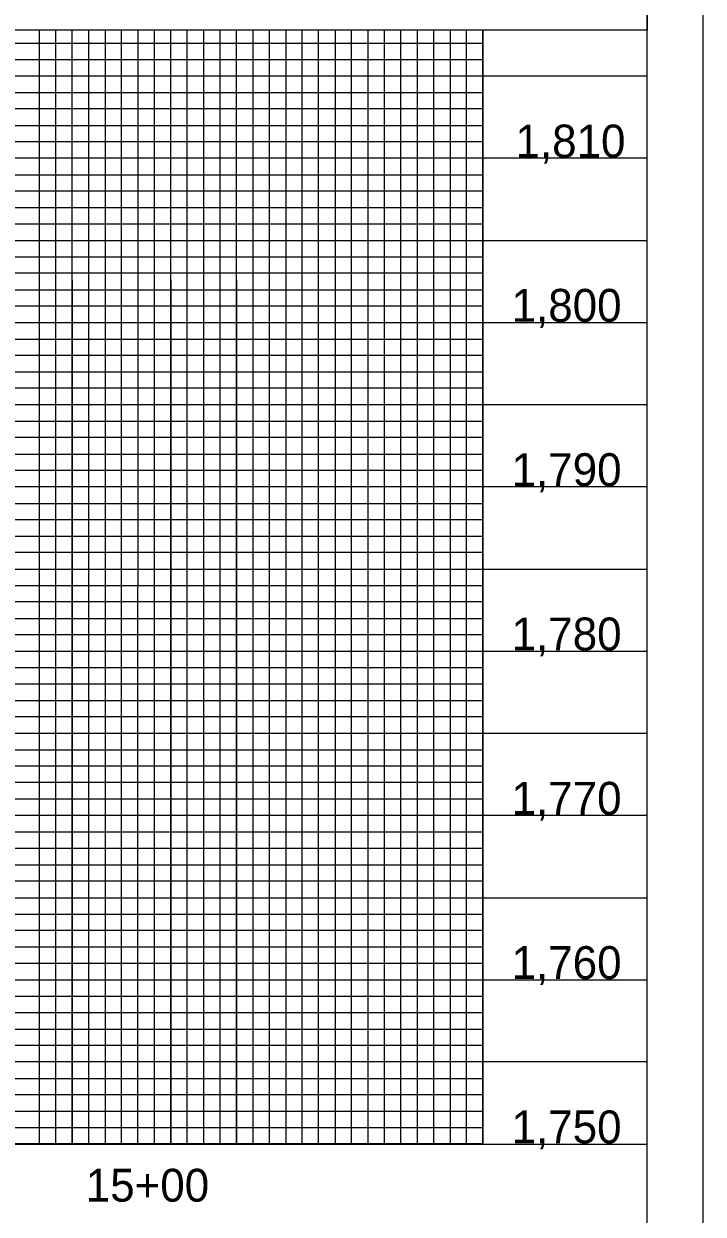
# Model space of a CAD drawing. Extents: x 505602 to 507705, y 483109 to 484209.
# Drawn here: x 507079.4 to 507286.1, y 483662.4 to 484024.6 of the extents above; entities that cross this region are included whole.
import ezdxf

# ---------------------------------------------------------------- set-up
doc = ezdxf.new("R2010")
doc.units = 0
for name, color, linetype in [('Exist Vertical Profile Vertical Axis Label', 7, 'Continuous'), ('Sheet Layout Profile Border Port 1', 7, 'Continuous'), ('Sheet Plot Border Outside CELL', 7, 'Continuous'), ('Sheet Profile CELL', 7, 'Continuous'), ('Sheet Profile Grid Major CELL', 7, 'Continuous'), ('Sheet Profile Grid Middle CELL', 7, 'Continuous'), ('Sheet Profile Grid Minor CELL', 7, 'Continuous'), ('Sheet Sticker Exception Certification CELL', 7, 'Continuous')]:
    doc.layers.add(name, color=color, linetype=linetype)

msp = doc.modelspace()

# ---------------------------------------------------------------- linework, layer by layer
at = {"layer": 'Sheet Layout Profile Border Port 1'}
msp.add_lwpolyline([(506619.08, 484183.71), (506619.08, 483683.71), (507219.08, 483683.96), (507219.08, 484022.66), (507069.08, 484022.66), (507069.03, 484183.71)], close=True, dxfattribs=at)
at = {"layer": 'Sheet Plot Border Outside CELL'}
msp.add_lwpolyline([(505602.08, 483108.71), (507286.08, 483108.71), (507286.08, 484208.71), (505602.08, 484208.71)], close=True, dxfattribs=at)
at = {"layer": 'Sheet Profile CELL'}
msp.add_line((505769.08, 483683.71), (507269.08, 483683.71), dxfattribs=at)
msp.add_lwpolyline([(507269.08, 484183.71), (505769.08, 484183.71), (505769.08, 483133.71), (507269.08, 483133.71)], close=True, dxfattribs=at)
at = {"layer": 'Sheet Profile Grid Major CELL'}
for points in [[(507219.08, 484022.66), (507219.08, 483683.71), (507269.08, 483683.71), (507269.08, 484033.71)], [(507119.08, 484022.66), (507119.08, 483683.71), (507169.08, 483683.71), (507169.08, 483683.71), (507169.08, 484022.66)], [(507269.08, 483983.71), (505769.08, 483983.71), (505769.08, 483933.71), (507269.08, 483933.71)], [(507269.08, 483883.71), (505769.08, 483883.71), (505769.08, 483833.71), (507269.08, 483833.71)], [(507269.08, 483783.71), (505769.08, 483783.71), (505769.08, 483783.71), (505769.08, 483733.71), (507269.08, 483733.71)]]:
    msp.add_lwpolyline(points, dxfattribs=at)
at = {"layer": 'Sheet Profile Grid Middle CELL'}
for points in [[(506644.08, 483683.71), (506694.08, 483683.71), (506694.08, 484183.71), (506744.08, 484183.71), (506744.08, 483683.71), (506794.08, 483683.71), (506794.08, 484183.71), (506844.08, 484183.71), (506844.08, 483683.71), (506894.08, 483683.71), (506894.08, 484183.71), (506944.08, 484183.71), (506944.08, 483683.71), (506994.08, 483683.71), (506994.08, 484183.71), (507044.08, 484183.71), (507044.08, 483683.71), (507094.08, 483683.71), (507094.08, 484022.66)], [(507094.08, 483946.51), (507094.08, 483683.71), (507144.08, 483683.71), (507144.08, 484022.66)], [(507144.08, 483946.51), (507144.08, 483683.71), (507194.08, 483683.71), (507194.08, 484022.66)], [(507269.08, 484008.71), (505769.08, 484008.71), (505769.08, 483958.71), (507094.08, 483958.71)], [(507094.08, 483958.71), (507269.08, 483958.71)], [(507269.08, 483908.71), (505769.08, 483908.71), (505769.08, 483858.71), (507269.08, 483858.71)], [(507269.08, 483808.71), (505769.08, 483808.71), (505769.08, 483758.71), (507269.08, 483758.71)], [(507269.08, 483708.71), (505769.08, 483708.71)]]:
    msp.add_lwpolyline(points, dxfattribs=at)
at = {"layer": 'Sheet Profile Grid Minor CELL'}
for p, q in [((505819.08, 484018.71), (507219.08, 484018.71)), ((507219.08, 483998.71), (505819.08, 483998.71)), ((505819.08, 483993.71), (507219.08, 483993.71)), ((507219.08, 483973.71), (505819.08, 483973.71)), ((505819.08, 483968.71), (507219.08, 483968.71)), ((507219.08, 483948.71), (505819.08, 483948.71)), ((505819.08, 483943.71), (507219.08, 483943.71)), ((507219.08, 483938.71), (505819.08, 483938.71)), ((505819.08, 483928.71), (507219.08, 483928.71)), ((507219.08, 483923.71), (505819.08, 483923.71)), ((505819.08, 483918.71), (507219.08, 483918.71)), ((507219.08, 483913.71), (505819.08, 483913.71)), ((505819.08, 483903.71), (507219.08, 483903.71)), ((507219.08, 483898.71), (505819.08, 483898.71)), ((505819.08, 483893.71), (507219.08, 483893.71)), ((507219.08, 483888.71), (505819.08, 483888.71)), ((505819.08, 483878.71), (507219.08, 483878.71)), ((507219.08, 483873.71), (505819.08, 483873.71)), ((505819.08, 483868.71), (507219.08, 483868.71)), ((507219.08, 483863.71), (505819.08, 483863.71)), ((505819.08, 483853.71), (507219.08, 483853.71)), ((507219.08, 483848.71), (505819.08, 483848.71)), ((505819.08, 483843.71), (507219.08, 483843.71)), ((507219.08, 483838.71), (505819.08, 483838.71)), ((505819.08, 483828.71), (507219.08, 483828.71)), ((507219.08, 483823.71), (505819.08, 483823.71)), ((505819.08, 483818.71), (507219.08, 483818.71)), ((507219.08, 483813.71), (505819.08, 483813.71)), ((505819.08, 483803.71), (507219.08, 483803.71)), ((507219.08, 483798.71), (505819.08, 483798.71)), ((507219.08, 483793.71), (505819.08, 483793.71)), ((507219.08, 483788.71), (505819.08, 483788.71)), ((505819.08, 483778.71), (507219.08, 483778.71)), ((507219.08, 483773.71), (505819.08, 483773.71)), ((505819.08, 483768.71), (507219.08, 483768.71)), ((507219.08, 483763.71), (505819.08, 483763.71)), ((505819.08, 483753.71), (507219.08, 483753.71)), ((507219.08, 483748.71), (505819.08, 483748.71)), ((505819.08, 483743.71), (507219.08, 483743.71)), ((507219.08, 483738.71), (505819.08, 483738.71)), ((505819.08, 483728.71), (507219.08, 483728.71)), ((507219.08, 483723.71), (505819.08, 483723.71)), ((505819.08, 483718.71), (507219.08, 483718.71)), ((507219.08, 483713.71), (505819.08, 483713.71)), ((505819.08, 483703.71), (507219.08, 483703.71)), ((507219.08, 483698.71), (505819.08, 483698.71)), ((505819.08, 483693.71), (507219.08, 483693.71))]:
    msp.add_line(p, q, dxfattribs=at)
for points in [[(507084.08, 484022.66), (507084.08, 483683.71), (507089.08, 483683.71), (507089.08, 484022.66)], [(507099.08, 484022.66), (507099.08, 483683.71), (507099.08, 483683.71), (507104.08, 483683.71), (507109.08, 483683.71), (507109.08, 484022.66)], [(507104.08, 484022.66), (507104.08, 483683.71)], [(507114.07, 484022.66), (507113.98, 483683.76), (507118.98, 483683.76), (507124.08, 483683.71), (507124.08, 484022.66)], [(507124.08, 483946.51), (507124.08, 483683.71), (507129.08, 483683.71), (507129.08, 484022.66)], [(507134.08, 484022.66), (507134.08, 483683.71), (507139.08, 483683.71), (507139.08, 484022.66)], [(507149.08, 484022.66), (507149.08, 483683.71), (507154.08, 483683.71), (507154.08, 484022.66)], [(507159.08, 484022.66), (507159.08, 483683.71), (507164.08, 483683.71), (507164.08, 484022.66)], [(507174.08, 484022.66), (507174.08, 483683.71), (507179.08, 483683.71), (507179.08, 484022.66)], [(507184.08, 484022.66), (507184.08, 483683.71), (507189.08, 483683.71), (507189.08, 484022.66)], [(507199.08, 484022.66), (507199.08, 483683.71), (507204.08, 483683.71), (507204.08, 484022.66)], [(507209.08, 484022.66), (507209.08, 483683.71), (507214.08, 483683.71), (507214.08, 484022.66)], [(507219.08, 484013.71), (505819.08, 484013.71), (505819.08, 484003.71), (507219.08, 484003.71)], [(507219.08, 483988.71), (505819.08, 483988.71), (505819.08, 483978.71), (507219.08, 483978.71)], [(507219.08, 483963.71), (505819.08, 483963.71), (505819.08, 483953.71), (507219.08, 483953.71)], [(507219.08, 483688.71), (505819.08, 483688.71)]]:
    msp.add_lwpolyline(points, dxfattribs=at)
at = {"layer": 'Sheet Sticker Exception Certification CELL'}
for p, q in [((507269.07, 484046.15), (507269.07, 484022.65)), ((507269.07, 484046.15), (507269.07, 484022.65)), ((507269.07, 484022.66), (507069.03, 484022.66)), ((507269.07, 484022.66), (507069.03, 484022.66))]:
    msp.add_line(p, q, dxfattribs=at)

# ---------------------------------------------------------------- texts
at = {"layer": 'Exist Vertical Profile Vertical Axis Label'}
for s, p in [('1,810', (507228.97, 483983.96)), ('1,800', (507227.78, 483933.96)), ('1,790', (507227.78, 483883.96)), ('1,780', (507227.78, 483833.96)), ('1,770', (507227.78, 483783.96)), ('1,760', (507227.78, 483733.96)), ('1,750', (507227.78, 483683.96)), ('15+00', (507098.21, 483666.21))]:
    msp.add_text(s, height=10, dxfattribs=at).set_placement(p)

doc.saveas('drawing.dxf')
